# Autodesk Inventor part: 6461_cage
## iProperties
Author: Ole Germer
Shininess: 64.0
Angle Display Precision: 2
Document Length Units: 11272
Document Angle Units: 11286
Document Time Units: 11279
Document Mass Units: 11290
Document Length Units Precision: 3
Document Angle Units Precision: 2
Compacted: True
PropertySet Name: _Private Model Information
Created: 2002-10
Part Number: 6461_cage
Material: Stainless Steel, Austenitic
Document SubType Name: Modeling
Designer: Ole Germer
Control State: 0
Master: False
Checked Out: False
PropertySet Name: Design Tracking Control
Density: 0.0
Volumn: 0.0
Area: 0.0
PropertySet Name: Model Information
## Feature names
1. Revolution1
2. Extrusion1
3. Circular Pattern1
